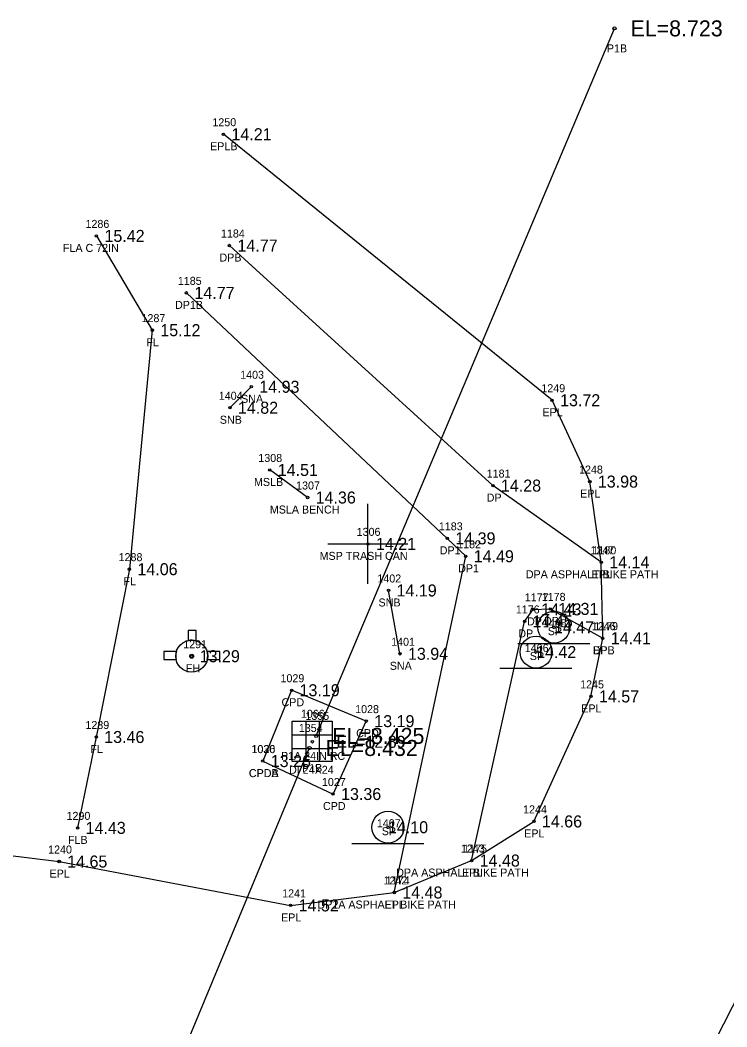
# Model space of a CAD drawing. Extents: x 2072307 to 2072993, y 127574 to 129736.
# Drawn here: x 2072786.6 to 2072874.9, y 128591.5 to 128717.2 of the extents above; entities that cross this region are included whole.
import ezdxf

# ---------------------------------------------------------------- set-up
doc = ezdxf.new("R2010")
doc.units = 0
for name, color, linetype in [('RD_EX_BldgApp', 7, 'Continuous'), ('RD_EX_BldgApp_txCode', 7, 'Continuous'), ('RD_EX_Conc', 7, 'Continuous'), ('RD_EX_Conc_txCode', 7, 'Continuous'), ('RD_EX_DR_Inlet', 7, 'Continuous'), ('RD_EX_DR_Inlet_txCode', 7, 'Continuous'), ('RD_EX_DR_Pipe', 7, 'Continuous'), ('RD_EX_DR_Pipe_txCode', 7, 'Continuous'), ('RD_EX_Driveway', 7, 'Continuous'), ('RD_EX_Driveway_txCode', 7, 'Continuous'), ('RD_EX_Fence_Other', 7, 'Continuous'), ('RD_EX_Fence_Other_txCode', 7, 'Continuous'), ('RD_EX_Misc', 7, 'Continuous'), ('RD_EX_Misc_txCode', 7, 'Continuous'), ('RD_EX_Road', 7, 'Continuous'), ('RD_EX_Road_txCode', 7, 'Continuous'), ('RD_EX_TX_BldgApp_ELEV', 7, 'Continuous'), ('RD_EX_TX_Conc_ELEV', 7, 'Continuous'), ('RD_EX_TX_DR_Inlet_ELEV', 7, 'Continuous'), ('RD_EX_TX_Driveway_ELEV', 7, 'Continuous'), ('RD_EX_TX_Fence_Other_ELEV', 7, 'Continuous'), ('RD_EX_TX_Misc_ELEV', 7, 'Continuous'), ('RD_EX_TX_Road_ELEV', 7, 'Continuous'), ('RD_EX_TX_UT_ELEV', 7, 'Continuous'), ('RD_EX_UT', 7, 'Continuous'), ('RD_EX_UT_txCode', 7, 'Continuous'), ('RD_SMD_Locator', 7, 'Continuous'), ('RD_TX_Pipe_ElevEX', 7, 'Continuous')]:
    doc.layers.add(name, color=color, linetype=linetype)

msp = doc.modelspace()

# ---------------------------------------------------------------- linework, layer by layer
at = {"layer": 'RD_EX_BldgApp'}
for p, q in [((2072815.48, 128671.46), (2072812.81, 128668.84)), ((2072834.06, 128638.11), (2072832.63, 128646.02)), ((2072848.79, 128639.41), (2072857.79, 128639.41)), ((2072846.55, 128636.3), (2072855.55, 128636.3)), ((2072828.04, 128614.42), (2072837.04, 128614.42))]:
    msp.add_line(p, q, dxfattribs=at)
for centre in [(2072853.3, 128641.43), (2072851.07, 128638.33), (2072832.56, 128616.45)]:
    msp.add_circle(centre, 2, dxfattribs=at)
at = {"layer": 'RD_EX_Conc'}
msp.add_lwpolyline([(2072816.91, 128624.71), (2072825.7, 128620.6), (2072829.85, 128629.7), (2072820.51, 128633.56), (2072816.91, 128624.71)], dxfattribs=at)
at = {"layer": 'RD_EX_DR_Inlet'}
for p, q in [((2072822.28, 128629.68), (2072822.28, 128624.68)), ((2072823.98, 128629.68), (2072823.98, 128624.68)), ((2072820.58, 128627.98), (2072825.58, 128627.98)), ((2072820.58, 128626.28), (2072825.58, 128626.28))]:
    msp.add_line(p, q, dxfattribs=at)
msp.add_lwpolyline([(2072820.58, 128624.68), (2072820.58, 128629.68), (2072825.58, 128629.68), (2072825.58, 128624.68)], close=True, dxfattribs=at)
at = {"layer": 'RD_EX_DR_Pipe'}
for p, q in [((2072823.59, 128627.86), (2072860.87, 128716.22)), ((2072791.86, 128552.08), (2072822.76, 128626.35))]:
    msp.add_line(p, q, dxfattribs=at)
at = {"layer": 'RD_EX_Driveway'}
for points in [[(2072859.22, 128649.54), (2072845.68, 128659.12), (2072812.75, 128689.1)], [(2072833.35, 128608.3), (2072842.28, 128650.29), (2072839.98, 128652.53), (2072807.37, 128683.19)], [(2072843.02, 128612.29), (2072849.63, 128642.15), (2072850.72, 128643.66), (2072852.84, 128643.72), (2072859.4, 128640.06)]]:
    msp.add_lwpolyline(points, dxfattribs=at)
at = {"layer": 'RD_EX_Fence_Other'}
msp.add_lwpolyline([(2072796.13, 128690.3), (2072803.11, 128678.53), (2072800.25, 128648.68), (2072796.1, 128627.72), (2072793.77, 128616.37)], dxfattribs=at)
at = {"layer": 'RD_EX_Misc'}
for p, q in [((2072822.52, 128657.63), (2072817.79, 128661.07)), ((2072830.06, 128646.84), (2072830.06, 128656.84)), ((2072825.06, 128651.84), (2072835.06, 128651.84))]:
    msp.add_line(p, q, dxfattribs=at)
at = {"layer": 'RD_EX_Road'}
for points in [[(2072734.64, 128675.72), (2072738.84, 128675.55), (2072739.33, 128643.18), (2072740.56, 128632.37), (2072745.62, 128623.39), (2072752.36, 128618.05), (2072766.47, 128615.25), (2072791.47, 128612.17), (2072820.4, 128606.69), (2072833.35, 128608.3), (2072843.02, 128612.29), (2072850.8, 128617.18), (2072857.93, 128632.79), (2072859.4, 128640.06), (2072859.22, 128649.54), (2072857.79, 128659.62), (2072853.07, 128669.78), (2072812, 128703)], [(2072789.45, 128345.69), (2072789.46, 128382.93), (2072788.01, 128408.09), (2072794.06, 128431.26), (2072804.3, 128453.88), (2072840.7, 128525.64), (2072876.68, 128596.08), (2072888.72, 128617.36), (2072893.24, 128622.62), (2072899.84, 128627.36), (2072910.72, 128631.76), (2072918.79, 128632.23), (2072935.82, 128627.02), (2072957.37, 128619.98)]]:
    msp.add_lwpolyline(points, dxfattribs=at)
at = {"layer": 'RD_EX_UT'}
for p, q in [((2072807.57, 128641.03), (2072807.57, 128639.75)), ((2072808.57, 128641.03), (2072807.57, 128641.03)), ((2072808.57, 128639.73), (2072808.57, 128641.03)), ((2072806.12, 128638.38), (2072804.56, 128638.38)), ((2072804.56, 128638.38), (2072804.56, 128637.38)), ((2072811.56, 128638.38), (2072809.95, 128638.38)), ((2072811.56, 128637.38), (2072811.56, 128638.38)), ((2072804.56, 128637.38), (2072806.08, 128637.38)), ((2072809.99, 128637.38), (2072811.56, 128637.38))]:
    msp.add_line(p, q, dxfattribs=at)
for radius in [2, 0.25]:
    msp.add_circle((2072808.03, 128637.81), radius, dxfattribs=at)
for start, end in [(74.2455, 103.2128), (163.3387, 192.315), (347.685, 16.6613)]:
    msp.add_arc((2072808.03, 128637.81), 2, start, end, dxfattribs=at)
at = {"layer": 'RD_SMD_Locator'}
for centre, radius in [((2072860.87, 128716.22), 0.2), ((2072812, 128703), 0.15), ((2072796.13, 128690.3), 0.15), ((2072812.75, 128689.1), 0.15), ((2072807.37, 128683.19), 0.15), ((2072803.11, 128678.53), 0.15), ((2072815.48, 128671.46), 0.15), ((2072812.81, 128668.84), 0.15), ((2072853.07, 128669.78), 0.15), ((2072817.79, 128661.07), 0.15), ((2072845.68, 128659.12), 0.15), ((2072857.79, 128659.62), 0.15), ((2072822.52, 128657.63), 0.15), ((2072839.98, 128652.53), 0.15), ((2072830.06, 128651.84), 0.15), ((2072842.28, 128650.29), 0.15), ((2072859.22, 128649.54), 0.15), ((2072859.22, 128649.54), 0.15), ((2072800.25, 128648.68), 0.15), ((2072832.63, 128646.02), 0.15), ((2072852.84, 128643.72), 0.15), ((2072850.72, 128643.66), 0.15), ((2072849.63, 128642.15), 0.15), ((2072853.3, 128641.43), 0.15), ((2072859.4, 128640.06), 0.15), ((2072859.4, 128640.06), 0.15), ((2072808.03, 128637.81), 0.15), ((2072834.06, 128638.11), 0.15), ((2072851.07, 128638.33), 0.15), ((2072820.51, 128633.56), 0.15), ((2072857.93, 128632.79), 0.15), ((2072829.85, 128629.7), 0.15), ((2072796.1, 128627.72), 0.15), ((2072823.59, 128627.86), 0.2), ((2072822.76, 128626.35), 0.2), ((2072823.12, 128627.12), 0.15), ((2072816.91, 128624.71), 0.15), ((2072816.91, 128624.71), 0.15), ((2072825.7, 128620.6), 0.15), ((2072793.77, 128616.37), 0.15), ((2072832.56, 128616.45), 0.15), ((2072850.8, 128617.18), 0.15), ((2072843.02, 128612.29), 0.15), ((2072843.02, 128612.29), 0.15), ((2072791.47, 128612.17), 0.15), ((2072833.35, 128608.3), 0.15), ((2072833.35, 128608.3), 0.15), ((2072820.4, 128606.69), 0.15)]:
    msp.add_circle(centre, radius, dxfattribs=at)

# ---------------------------------------------------------------- texts
at = {"layer": 'RD_EX_BldgApp_txCode'}
for s, p in [('1403', (2072814.09, 128672.46)), ('1404', (2072811.42, 128669.84)), ('SNA', (2072814.21, 128669.46)), ('SNB', (2072811.55, 128666.84)), ('1402', (2072831.24, 128647.02)), ('SNB', (2072831.38, 128644.02)), ('1405', (2072851.92, 128641.43)), ('SP', (2072852.53, 128640.43)), ('1401', (2072832.96, 128639.11)), ('1406', (2072849.66, 128638.33)), ('SP', (2072850.29, 128637.33)), ('SNA', (2072832.79, 128636.11)), ('1407', (2072831.17, 128616.45)), ('SP', (2072831.78, 128615.45))]:
    msp.add_text(s, height=1, dxfattribs=at).set_placement(p)
at = {"layer": 'RD_EX_Conc_txCode'}
for s, p in [('1029', (2072819.13, 128634.56)), ('CPD', (2072819.26, 128631.56)), ('1028', (2072828.46, 128630.7)), ('CPD', (2072828.59, 128627.7)), ('1030', (2072815.49, 128625.71)), ('1026', (2072815.51, 128625.71)), ('CPDA', (2072815.17, 128622.71)), ('CPDB', (2072815.19, 128622.71)), ('1027', (2072824.31, 128621.6)), ('CPD', (2072824.44, 128618.6))]:
    msp.add_text(s, height=1, dxfattribs=at).set_placement(p)
at = {"layer": 'RD_EX_DR_Inlet_txCode'}
for s, p in [('1066', (2072821.68, 128630.12)), ('DI 24X24', (2072820.2, 128623.12))]:
    msp.add_text(s, height=1, dxfattribs=at).set_placement(p)
at = {"layer": 'RD_EX_DR_Pipe_txCode'}
for s, p in [('P1B', (2072859.92, 128713.22)), ('1355', (2072822.24, 128629.86)), ('1354', (2072821.42, 128628.35)), ('P1A 24IN RC', (2072819.19, 128624.86)), ('P1B', (2072821.82, 128623.35))]:
    msp.add_text(s, height=1, dxfattribs=at).set_placement(p)
at = {"layer": 'RD_EX_Driveway_txCode'}
for s, p in [('1184', (2072811.69, 128690.1)), ('DPB', (2072811.5, 128687.1)), ('1185', (2072806.3, 128684.19)), ('DP1B', (2072805.95, 128681.19)), ('1181', (2072844.9, 128660.12)), ('DP', (2072844.9, 128657.12)), ('1183', (2072838.92, 128653.53)), ('DP1', (2072839.03, 128650.53)), ('1182', (2072841.21, 128651.29)), ('1180', (2072858.12, 128650.54)), ('DP1', (2072841.33, 128648.29)), ('DPA ASPHALT BIKE PATH', (2072849.79, 128647.54)), ('1177', (2072849.66, 128644.66)), ('1178', (2072851.78, 128644.72)), ('1176', (2072848.54, 128643.15)), ('DP', (2072849.94, 128641.66)), ('DP', (2072852.06, 128641.72)), ('1179', (2072858.34, 128641.06)), ('DP', (2072848.85, 128640.15)), ('DPB', (2072858.15, 128638.06)), ('1175', (2072841.96, 128613.29)), ('DPA ASPHALT BIKE PATH', (2072833.59, 128610.29)), ('1174', (2072832.28, 128609.3)), ('DP1A ASPHALT BIKE PATH', (2072823.75, 128606.3))]:
    msp.add_text(s, height=1, dxfattribs=at).set_placement(p)
at = {"layer": 'RD_EX_Fence_Other_txCode'}
for s, p in [('1286', (2072794.76, 128691.3)), ('FLA C 72IN', (2072791.94, 128688.3)), ('1287', (2072801.76, 128679.53)), ('FL', (2072802.37, 128676.53)), ('1288', (2072798.9, 128649.68)), ('FL', (2072799.51, 128646.68)), ('1289', (2072794.75, 128628.72)), ('FL', (2072795.37, 128625.72)), ('1290', (2072792.39, 128617.37)), ('FLB', (2072792.57, 128614.37))]:
    msp.add_text(s, height=1, dxfattribs=at).set_placement(p)
at = {"layer": 'RD_EX_Misc_txCode'}
for s, p in [('1308', (2072816.36, 128662.07)), ('MSLB', (2072815.82, 128659.07)), ('1307', (2072821.08, 128658.63)), ('MSLA BENCH', (2072817.8, 128655.63)), ('1306', (2072828.65, 128652.84)), ('MSP TRASH CAN', (2072824.02, 128649.84))]:
    msp.add_text(s, height=1, dxfattribs=at).set_placement(p)
at = {"layer": 'RD_EX_Road_txCode'}
for s, p in [('1250', (2072810.62, 128704)), ('EPLB', (2072810.33, 128701)), ('1249', (2072851.73, 128670.78)), ('EPL', (2072851.87, 128667.78)), ('1248', (2072856.44, 128660.62)), ('EPL', (2072856.58, 128657.62)), ('1247', (2072857.87, 128650.54)), ('EPL', (2072858.01, 128647.54)), ('1246', (2072858.03, 128641.06)), ('EPL', (2072858.2, 128638.06)), ('1245', (2072856.58, 128633.79)), ('EPL', (2072856.72, 128630.79)), ('1244', (2072849.45, 128618.18)), ('EPL', (2072849.59, 128615.18)), ('1240', (2072790.09, 128613.17)), ('1243', (2072841.68, 128613.29)), ('EPL', (2072790.27, 128610.17)), ('EPL', (2072841.82, 128610.29)), ('1242', (2072832, 128609.3)), ('1241', (2072819.34, 128607.69)), ('EPL', (2072832.14, 128606.3)), ('EPL', (2072819.2, 128604.69))]:
    msp.add_text(s, height=1, dxfattribs=at).set_placement(p)
at = {"layer": 'RD_EX_TX_BldgApp_ELEV'}
for s, p in [('14.93', (2072816.48, 128670.71)), ('14.82', (2072813.81, 128668.09)), ('14.19', (2072833.63, 128645.27)), ('14.47', (2072853.3, 128640.68)), ('13.94', (2072835.06, 128637.36)), ('14.42', (2072851.07, 128637.58)), ('14.10', (2072832.56, 128615.7))]:
    msp.add_text(s, height=1.5, dxfattribs=at).set_placement(p)
at = {"layer": 'RD_EX_TX_Conc_ELEV'}
for s, p in [('13.19', (2072821.51, 128632.81)), ('13.19', (2072830.85, 128628.95)), ('13.26', (2072817.91, 128623.96)), ('13.26', (2072817.91, 128623.96)), ('13.36', (2072826.7, 128619.85))]:
    msp.add_text(s, height=1.5, dxfattribs=at).set_placement(p)
at = {"layer": 'RD_EX_TX_DR_Inlet_ELEV'}
msp.add_text('EL=12.89', height=1.5, dxfattribs=at).set_placement((2072826.12, 128626.37))
at = {"layer": 'RD_EX_TX_Driveway_ELEV'}
for s, p in [('14.77', (2072813.75, 128688.35)), ('14.77', (2072808.37, 128682.44)), ('14.28', (2072846.68, 128658.37)), ('14.39', (2072840.98, 128651.78)), ('14.49', (2072843.28, 128649.54)), ('14.14', (2072860.22, 128648.79)), ('14.43', (2072851.72, 128642.91)), ('14.31', (2072853.84, 128642.97)), ('14.45', (2072850.63, 128641.4)), ('14.41', (2072860.4, 128639.31)), ('14.48', (2072844.02, 128611.54)), ('14.48', (2072834.35, 128607.55))]:
    msp.add_text(s, height=1.5, dxfattribs=at).set_placement(p)
at = {"layer": 'RD_EX_TX_Fence_Other_ELEV'}
for s, p in [('15.42', (2072797.13, 128689.55)), ('15.12', (2072804.11, 128677.78)), ('14.06', (2072801.25, 128647.93)), ('13.46', (2072797.1, 128626.97)), ('14.43', (2072794.77, 128615.62))]:
    msp.add_text(s, height=1.5, dxfattribs=at).set_placement(p)
at = {"layer": 'RD_EX_TX_Misc_ELEV'}
for s, p in [('14.51', (2072818.79, 128660.32)), ('14.36', (2072823.52, 128656.88)), ('14.21', (2072831.06, 128651.09))]:
    msp.add_text(s, height=1.5, dxfattribs=at).set_placement(p)
at = {"layer": 'RD_EX_TX_Road_ELEV'}
for s, p in [('14.21', (2072813, 128702.25)), ('13.72', (2072854.07, 128669.03)), ('13.98', (2072858.79, 128658.87)), ('14.14', (2072860.22, 128648.79)), ('14.41', (2072860.4, 128639.31)), ('14.57', (2072858.93, 128632.04)), ('14.66', (2072851.8, 128616.43)), ('14.65', (2072792.47, 128611.42)), ('14.48', (2072844.02, 128611.54)), ('14.48', (2072834.35, 128607.55)), ('14.52', (2072821.4, 128605.94))]:
    msp.add_text(s, height=1.5, dxfattribs=at).set_placement(p)
at = {"layer": 'RD_EX_TX_UT_ELEV'}
msp.add_text('13.29', height=1.5, dxfattribs=at).set_placement((2072809.03, 128637.06))
at = {"layer": 'RD_EX_UT_txCode'}
for s, p in [('1291', (2072806.97, 128638.81)), ('FH', (2072807.3, 128635.81))]:
    msp.add_text(s, height=1, dxfattribs=at).set_placement(p)
at = {"layer": 'RD_TX_Pipe_ElevEX'}
for s, p in [('EL=8.723', (2072862.87, 128715.22)), ('EL=8.425', (2072825.59, 128626.86)), ('EL=8.432', (2072824.76, 128625.35))]:
    msp.add_text(s, height=2, dxfattribs=at).set_placement(p)

doc.saveas('drawing.dxf')
